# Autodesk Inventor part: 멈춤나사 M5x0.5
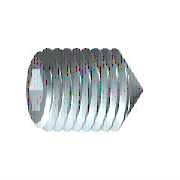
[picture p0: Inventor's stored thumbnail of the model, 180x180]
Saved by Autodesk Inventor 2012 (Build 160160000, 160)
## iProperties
Company: 한국ATC센터
IsCustomPart: 1
Created: 2014-11
Part Number: 멈춤나사 M5x0.5
Material: 강, 연강
Description: 6각 소켓 머리 없는 멈춤 나사
Document SubType Name: Modeling
Standard: KS B 1028
Designer: KYOUNG IL JANG
Standards Organization: KS
Language: ko-KR
Size Designation: 원추점 M5x10
Categories: <MemberInstance><Categories><Category DisplayName="조임쇠" InternalName="e4da775c-781d-43d5-af7c-5136215cf5a6" Mnemonic="FSTN"><Category DisplayName="볼트" InternalN
Density: 7.86 g/cm^3
Mass: 1.16912 g
Surface Area: 1.91683 cm^2
Volume: 0.148743 cm^3
Author: KYOUNG IL JANG
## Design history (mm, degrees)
revolve "본체" stored, may be unused: angle "d6" = 90 deg
sketch "스케치2"
  geometry: L1 (-0.722, 1.25)-(0.722, 1.25); L2 (0.722, 1.25)-(1.443, 0); L3 (1.443, 0)-(0.722, -1.25); L4 (0.722, -1.25)-(-0.722, -1.25); L5 (-0.722, -1.25)-(-1.443, 0); L6 (-1.443, 0)-(-0.722, 1.25); 3 further points
  constraints: 12 end point, 1 coincident, 1 horizontal, 13 other
extrude "슬롯" join sketch "스케치2" taper "d7" = 0 deg; stored distance "d21" = 10
workaxis "Work Axis1"
workplane "Work Plane1"
body "Solid1"
feature "스레드" dims "d12" = 10 (= NLG), "d13" = 0
chamfer "모따기1" distance "d8" = 2.25 (computed from NND, SPD, FAWI); stored, may be unused: angle "d9" = 45 deg (= FAWI), second distance "d34" = 2.25 (computed from NND, SPD, FAWI)
chamfer "모따기2" distance "d10" = 0.49076 (= -0.5 x GD1 + 0.5 x NND); stored, may be unused: angle "d11" = 45 deg (= FAWI), second distance "d35" = 0.49076 (= -0.5 x GD1 + 0.5 x NND)
sketch "스케치1"
  geometry: L1 (0, 0)-(6.167, 0); L2 (10, 1.443)-(10, 2.5); L3 (10, 2.5)-(0, 2.5); L4 (10, 1.443)-(7, 1.443); L5 (7, 1.443)-(6.167, 0); L6 (0, -0.5)-(0, 3) reference; L7 (0, 2.5)-(0, 0)
  constraints: 13 end point, 3 parallel, 1 collinear, 1 perpendicular, 1 point on line
  dimensions: "d0" = 3 distance of L2.start L4.end (= INTI); "d1" = 60 deg angle of L5 L1; "d2" = 5 diameter of L3 L1 (= NND); "d3" = 2.88675 diameter of L4 L1 (= 1.1547 x SW); "d5" = 10 distance from line of L2 L3.end (= NLG)
other parameters: "NND" = 5 [user parameter; used in 5 equation terms], "NLG" = 10 [user parameter; used in 2 equation terms], "INTI" = 3 [user parameter; used in 1 equation term], "FAWI" = 45 deg [user parameter; used in 4 equation terms], "SW" = 2.5 [user parameter; used in 2 equation terms], "GD1" = 4.01848 (= THREADDIA - 1.2269 x PTC) [user parameter; used in 2 equation terms], "d4" = 0, "FAWI1" = 45 deg [user parameter], "SPD" = 0.5 [user parameter; used in 2 equation terms], "d36" = 0, "d37" = 0, "GUL" = 0.49076 (= 0.61345 x PTC) [user parameter], "TPU" = 12.5 (computed from PTC) [user parameter], "TOA" = 30 deg [user parameter], "THREADDIA" = 5 [user parameter; used in 1 equation term], "PTC" = 0.8 [user parameter; used in 4 equation terms], "GAL" = 0.49076 (= 0.61345 x PTC) [user parameter], "E0" = 2.8875 (= 1.155 x SW) [user parameter]
